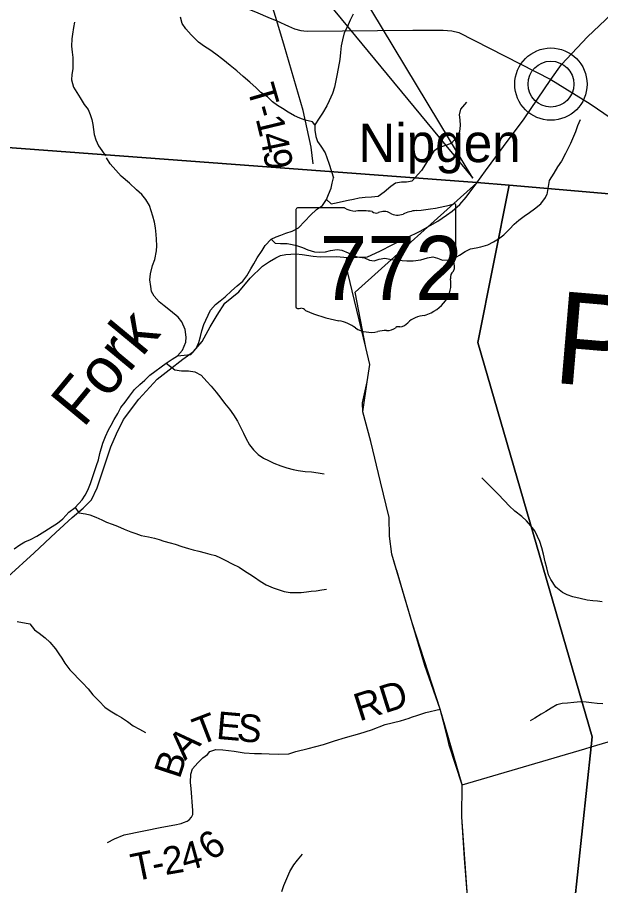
# Model space of a CAD drawing. Extents: x 0 to 34, y 0 to 22.
# Drawn here: x 3.817 to 5.019, y 17.795 to 19.582 of the extents above; entities that cross this region are included whole.
import ezdxf

# ---------------------------------------------------------------- set-up
doc = ezdxf.new("R2010")
doc.units = 0
for name, color, linetype in [('Default', 7, 'Continuous'), ('GM_X_County_Road', 7, 'Continuous'), ('GM_X_County_Text', 7, 'Continuous'), ('GM_X_Minor_River', 7, 'Continuous'), ('GM_X_Minor_River_Text', 7, 'Continuous'), ('GM_X_State_Location', 7, 'Continuous'), ('GM_X_State_Route', 7, 'Continuous'), ('GM_X_State_Shield', 7, 'Continuous'), ('GM_X_Township_Road', 7, 'Continuous'), ('GM_X_Township_Road_Text', 7, 'Continuous'), ('GM_X_Unincorporated', 7, 'Continuous'), ('GM_X_Unincorporated_Location', 7, 'Continuous'), ('GM_X_Unincorporated_Text', 7, 'Continuous'), ('SH_Cut_Line', 7, 'Continuous'), ('SH_Text', 7, 'Continuous')]:
    doc.layers.add(name, color=color, linetype=linetype)

msp = doc.modelspace()

# ---------------------------------------------------------------- linework, layer by layer
at = {"layer": 'Default'}
for p, q in [((4.5136, 19.0159), (4.7643, 19.2414)), ((4.5356, 18.9025), (4.5136, 19.0159)), ((4.5438, 18.8675), (4.5356, 18.9025)), ((4.5384, 18.8319), (4.5438, 18.8675)), ((4.5295, 18.7697), (4.5384, 18.8319)), ((4.5454, 18.7087), (4.5295, 18.7697)), ((4.5658, 18.6257), (4.5454, 18.7087)), ((4.5837, 18.5521), (4.5658, 18.6257)), ((4.5843, 18.5138), (4.5837, 18.5521)), ((4.5891, 18.4769), (4.5843, 18.5138)), ((4.6306, 18.3358), (4.5891, 18.4769)), ((4.6885, 18.1581), (4.6306, 18.3358)), ((4.7336, 18.0018), (4.6885, 18.1581)), ((4.7334, 17.9364), (4.7336, 18.0018)), ((4.7457, 17.7634), (4.7334, 17.9364))]:
    msp.add_line(p, q, dxfattribs=at)
msp.add_lwpolyline([(5.8621, 20.8), (2.8183, 20.8), (3.0244, 19.9995), (3.1893, 19.3592), (4.7641, 19.2419), (4.831, 19.2363), (5.1554, 19.2083), (5.1782, 19.2598), (5.5496, 20.1004), (5.5679, 20.1313), (5.5783, 20.1528), (5.5834, 20.1771), (5.5869, 20.1933), (5.5951, 20.2127), (5.6047, 20.2229), (5.6166, 20.2359)], close=True, dxfattribs=at)
for points in [[(4.7194, 16.7424), (4.6758, 16.8903), (4.9207, 17.3435), (4.9239, 17.3511), (4.937, 17.4953), (4.9996, 18.0806), (5.0018, 18.1008), (4.7661, 18.9124), (4.831, 19.2363), (4.7641, 19.2419), (3.1893, 19.3592), (2.7961, 19.3885), (2.2, 19.4329), (2.2, 14)], [(9, 14), (9, 18.8941), (8.8762, 18.9027), (8.0305, 18.9725), (6.8442, 19.0679), (6.226, 19.1161), (5.8337, 19.1499), (5.3224, 19.1939), (5.1554, 19.2083), (4.831, 19.2363), (4.7661, 18.9124), (5.0018, 18.1008), (4.9996, 18.0806), (4.937, 17.4953), (4.9239, 17.3511), (4.9207, 17.3435), (4.6758, 16.8903), (4.7194, 16.7424)]]:
    msp.add_lwpolyline(points, dxfattribs=at)
at = {"layer": 'GM_X_County_Road'}
for points in [[(4.3522, 19.5749), (4.1318, 20.2937), (4.0556, 20.5466), (3.9987, 20.7384), (3.9908, 20.7664), (3.9869, 20.7867), (3.9826, 20.8)], [(3.8106, 19.8567), (3.8307, 19.8474), (3.8722, 19.8295), (3.898, 19.8193), (3.9145, 19.8144), (3.9359, 19.8139), (3.9841, 19.8144), (4.0229, 19.8108), (4.0448, 19.8072), (4.067, 19.7996), (4.0907, 19.784), (4.1222, 19.7574), (4.1679, 19.715), (4.1864, 19.6956), (4.2033, 19.6726), (4.2288, 19.6388), (4.2486, 19.6219), (4.2614, 19.6133), (4.2873, 19.6013), (4.3128, 19.5911), (4.3334, 19.5824), (4.3522, 19.5749)], [(4.3522, 19.5749), (4.376, 19.5637), (4.3884, 19.5583), (4.4018, 19.5551), (4.408, 19.5543), (4.4144, 19.5531), (4.6324, 19.5555), (4.6948, 19.5557), (4.7129, 19.5541), (4.7273, 19.5504), (4.9164, 19.4541)], [(4.9164, 19.4541), (4.9979, 19.4035), (5.041, 19.3741), (5.05, 19.3665), (5.0594, 19.3519), (5.067, 19.3348), (5.076, 19.3196), (5.0812, 19.3138), (5.0898, 19.3083), (5.1026, 19.3049), (5.1266, 19.2989), (5.1414, 19.2924), (5.1511, 19.2846), (5.1627, 19.2744), (5.1784, 19.2593), (5.1867, 19.2531), (5.1893, 19.2513)], [(3.7978, 18.43), (3.8524, 18.4795), (3.8967, 18.5215), (3.9307, 18.5526), (3.9532, 18.5713), (3.97, 18.589), (3.982, 18.6135), (4.0098, 18.6978), (4.0218, 18.7247), (4.0365, 18.7541), (4.068, 18.7962), (4.1058, 18.8372), (4.1299, 18.8563), (4.1585, 18.878), (4.1806, 18.894), (4.1982, 18.9147), (4.2148, 18.9445), (4.2294, 18.969), (4.2452, 18.9935), (4.2738, 19.0171), (4.2972, 19.0449), (4.3224, 19.0697), (4.3368, 19.0796), (4.3498, 19.0866), (4.3594, 19.0914), (4.3704, 19.0934), (4.3913, 19.0951), (4.4043, 19.0937), (4.4271, 19.0903), (4.4416, 19.0886), (4.476, 19.0897), (4.497, 19.0874)]]:
    msp.add_lwpolyline(points, dxfattribs=at)
at = {"layer": 'GM_X_Minor_River'}
for points in [[(3.935, 19.5717), (3.9333, 19.5611), (3.9309, 19.5474), (3.93, 19.5376), (3.9291, 19.5224), (3.9305, 19.5103), (3.9315, 19.4993), (3.9321, 19.4883), (3.9316, 19.4761), (3.9295, 19.464), (3.9287, 19.453), (3.933, 19.4382), (3.9401, 19.4271), (3.9468, 19.416), (3.9549, 19.4023), (3.9631, 19.3919), (3.9675, 19.382), (3.9712, 19.3713), (3.9733, 19.3611), (3.9747, 19.3512), (3.9758, 19.3409), (3.979, 19.3295), (3.9846, 19.3173), (3.9912, 19.3078), (3.9994, 19.2967)], [(4.4305, 19.3606), (4.4256, 19.3667), (4.4102, 19.3703), (4.3993, 19.3743), (4.3887, 19.3793), (4.3756, 19.3867), (4.3636, 19.3944), (4.3534, 19.4006), (4.3433, 19.4083), (4.3325, 19.4183), (4.3193, 19.4275), (4.3092, 19.4368), (4.2965, 19.4483), (4.2827, 19.4602), (4.2699, 19.4717), (4.2561, 19.4829), (4.2411, 19.4952), (4.2265, 19.506), (4.2141, 19.5149), (4.2029, 19.5222), (4.1905, 19.5311), (4.1759, 19.5457), (4.1647, 19.558), (4.1573, 19.5691), (4.1533, 19.5824)], [(4.5095, 19.5884), (4.503, 19.576), (4.4967, 19.5616), (4.4909, 19.5503), (4.4874, 19.5356), (4.4846, 19.5231), (4.4829, 19.5094), (4.4816, 19.4954), (4.4787, 19.4769), (4.4755, 19.4625), (4.4707, 19.4383), (4.4668, 19.425), (4.4602, 19.4103), (4.4551, 19.3998), (4.4459, 19.3843), (4.4393, 19.3745), (4.4305, 19.3606), (4.43, 19.3496), (4.4321, 19.3363), (4.4361, 19.326), (4.4428, 19.3165), (4.4514, 19.3027), (4.455, 19.2932), (4.4602, 19.2795), (4.4687, 19.2512)], [(4.7426, 19.407), (4.7307, 19.3927), (4.7279, 19.3814), (4.7289, 19.3707), (4.7296, 19.3593), (4.7283, 19.3468), (4.724, 19.3367), (4.711, 19.3224), (4.6977, 19.3176), (4.6852, 19.3132), (4.6756, 19.3061), (4.666, 19.2922), (4.6583, 19.2798), (4.6498, 19.2666), (4.6311, 19.245)], [(4.977, 19.3708), (4.9712, 19.3584), (4.9673, 19.3463), (4.9568, 19.3225), (4.9521, 19.3127), (4.9467, 19.3018), (4.9382, 19.2859), (4.9301, 19.2743), (4.9228, 19.2611), (4.9128, 19.246), (4.9081, 19.2173)], [(3.811, 18.488), (3.8228, 18.4959), (3.833, 18.5019), (3.8444, 18.5068), (3.8577, 18.5139), (3.874, 18.524), (3.8892, 18.5338), (3.9002, 18.5409), (3.9112, 18.5496), (3.9238, 18.5632), (3.9363, 18.5726), (3.9511, 18.5888), (3.9572, 18.5986), (3.9626, 18.6085), (3.9683, 18.6221), (3.976, 18.6448), (3.9803, 18.6596), (3.9845, 18.6709), (3.9872, 18.6842), (3.9938, 18.7054), (3.9988, 18.7194), (4.0053, 18.7326), (4.0107, 18.7424), (4.0172, 18.7542), (4.0248, 18.7666), (4.0309, 18.7791), (4.0393, 18.7897), (4.0488, 18.8021), (4.0591, 18.8157), (4.0698, 18.8259), (4.08, 18.8349), (4.0903, 18.8455), (4.1009, 18.8526), (4.1135, 18.8624), (4.1241, 18.8699), (4.1366, 18.8782), (4.1476, 18.885), (4.1575, 18.8967), (4.1644, 18.9133), (4.1653, 18.9236), (4.1635, 18.9391), (4.1564, 18.9551), (4.1489, 18.9646), (4.1331, 18.9776), (4.1199, 18.9883), (4.1097, 18.996), (4.0992, 19.0078), (4.094, 19.0173), (4.0922, 19.028), (4.0907, 19.0416), (4.0916, 19.0541), (4.0962, 19.0712), (4.1008, 19.0837), (4.1043, 19.1011), (4.1048, 19.1113), (4.1041, 19.125), (4.1034, 19.1352), (4.1023, 19.1485), (4.1001, 19.1603), (4.0964, 19.1728), (4.0931, 19.1839), (4.0894, 19.1949), (4.0823, 19.2071), (4.0736, 19.217), (4.0627, 19.2265), (4.0488, 19.2403), (4.0315, 19.2552), (4.0206, 19.267), (4.009, 19.28), (4.0011, 19.2929)], [(4.1476, 18.885), (4.1751, 18.8881), (4.1857, 18.8999), (4.1914, 18.9128), (4.1948, 18.9246), (4.1978, 18.9368), (4.2016, 18.9493), (4.2058, 18.9588), (4.2104, 18.9691), (4.2157, 18.979), (4.2259, 18.9907), (4.2354, 18.998), (4.2453, 19.0067), (4.2589, 19.0189), (4.2703, 19.0291), (4.2821, 19.039), (4.2904, 19.05), (4.2988, 19.0645), (4.3049, 19.0747), (4.3117, 19.0869), (4.3219, 19.1017), (4.328, 19.112), (4.3402, 19.1253), (4.3508, 19.1302), (4.3603, 19.1336), (4.3705, 19.1374), (4.3838, 19.1416), (4.3967, 19.1488), (4.41, 19.1621), (4.4213, 19.1747), (4.4339, 19.1861), (4.4464, 19.1948), (4.4544, 19.207), (4.4585, 19.2172), (4.4639, 19.2305), (4.4661, 19.2404), (4.4687, 19.2512)], [(4.4544, 19.207), (4.4642, 19.1982), (4.4745, 19.1998), (4.4892, 19.2032), (4.4987, 19.2055), (4.5097, 19.2077), (4.5219, 19.2104), (4.534, 19.2115), (4.5473, 19.2123), (4.5606, 19.2138), (4.5735, 19.2229), (4.5871, 19.2347), (4.5966, 19.2412), (4.6091, 19.2431), (4.6194, 19.2434), (4.6311, 19.245)], [(4.3402, 19.1253), (4.3489, 19.1173), (4.3599, 19.1165), (4.3732, 19.1162), (4.3834, 19.1146), (4.3929, 19.112), (4.4046, 19.1078), (4.4156, 19.1032), (4.4297, 19.0994), (4.4395, 19.0987), (4.452, 19.0994), (4.4623, 19.1021), (4.4763, 19.104), (4.4858, 19.1025), (4.4987, 19.0971), (4.5082, 19.0926), (4.5176, 19.0891), (4.5328, 19.0869), (4.5431, 19.0823), (4.5525, 19.0804), (4.5628, 19.0842), (4.5745, 19.0861), (4.5886, 19.0834), (4.6003, 19.0819), (4.62, 19.0804), (4.6329, 19.0804), (4.6489, 19.0827), (4.6625, 19.0865), (4.6731, 19.0887), (4.683, 19.0861), (4.6936, 19.0823), (4.7065, 19.0827), (4.7187, 19.0865), (4.7281, 19.0922), (4.7403, 19.1001), (4.7509, 19.1051), (4.7627, 19.1077), (4.7721, 19.1093), (4.7866, 19.1134), (4.7987, 19.1199), (4.8089, 19.126), (4.8196, 19.134), (4.8313, 19.1457), (4.8408, 19.1564), (4.8503, 19.1644), (4.8617, 19.1723), (4.8723, 19.1803), (4.8829, 19.1875), (4.8958, 19.1982), (4.9053, 19.2111), (4.9081, 19.2173)], [(4.1241, 18.8699), (4.1417, 18.8566), (4.1557, 18.8543), (4.1701, 18.8539), (4.183, 18.852), (4.1963, 18.8456), (4.208, 18.8326), (4.2167, 18.8227), (4.227, 18.8106), (4.2365, 18.7977), (4.2444, 18.7874), (4.2543, 18.7756), (4.263, 18.7634), (4.271, 18.7505), (4.2789, 18.7353), (4.2831, 18.7258), (4.2884, 18.7159), (4.296, 18.7019), (4.3039, 18.6916), (4.3138, 18.6817), (4.3248, 18.6745), (4.3346, 18.6696), (4.346, 18.6642), (4.36, 18.6585), (4.3726, 18.6547), (4.3858, 18.6513), (4.3961, 18.6494), (4.4105, 18.6471), (4.4234, 18.646), (4.4374, 18.6441), (4.4499, 18.6422)], [(5.0225, 18.3787), (5.013, 18.3798), (5.0028, 18.381), (4.9914, 18.3825), (4.977, 18.3855), (4.9618, 18.389), (4.9501, 18.3928), (4.9406, 18.3981), (4.9269, 18.4087), (4.9167, 18.4247), (4.9118, 18.4346), (4.908, 18.4487), (4.905, 18.4608), (4.9012, 18.4768), (4.8982, 18.4897), (4.8936, 18.5026), (4.8891, 18.5133), (4.8834, 18.5247), (4.8754, 18.5349), (4.8667, 18.5452), (4.8565, 18.5543), (4.8421, 18.5657), (4.8307, 18.5764), (4.8212, 18.5863), (4.8072, 18.6011), (4.7969, 18.611), (4.7852, 18.6228), (4.7746, 18.6342)], [(3.9363, 18.5726), (3.9443, 18.5616), (3.9576, 18.5601), (3.9671, 18.5578), (3.9792, 18.5529), (3.9917, 18.5472), (4.0012, 18.543), (4.0129, 18.5384), (4.0239, 18.5346), (4.0372, 18.5282), (4.0516, 18.5225), (4.0615, 18.5191), (4.0725, 18.5153), (4.0876, 18.5122), (4.0998, 18.5099), (4.1093, 18.5069), (4.1195, 18.5038), (4.1324, 18.5), (4.1426, 18.4974), (4.1563, 18.4928), (4.1699, 18.4886), (4.1794, 18.486), (4.1912, 18.4829), (4.2041, 18.4795), (4.2139, 18.4769), (4.2257, 18.4738), (4.2359, 18.4692), (4.2454, 18.4647), (4.2598, 18.4571), (4.2742, 18.4499), (4.2856, 18.4426), (4.2962, 18.4358), (4.3061, 18.4293), (4.3178, 18.4213), (4.33, 18.4137), (4.3444, 18.4077), (4.3569, 18.4031), (4.3675, 18.4001), (4.3793, 18.3982), (4.3914, 18.3978), (4.4024, 18.3978), (4.4134, 18.3993), (4.4229, 18.4004), (4.4331, 18.4016), (4.4449, 18.4035), (4.4547, 18.405)], [(3.8171, 18.3385), (3.8429, 18.3332), (3.8528, 18.321), (3.8623, 18.3142), (3.8751, 18.3047), (3.8846, 18.2959), (3.896, 18.2823), (3.9032, 18.272), (3.9089, 18.2625), (3.9153, 18.2522), (3.9256, 18.2385), (3.9517, 18.2123), (3.9631, 18.1998), (3.9729, 18.1876), (3.9858, 18.1743), (3.998, 18.1617), (4.009, 18.1541), (4.0222, 18.1462), (4.0317, 18.1408), (4.0442, 18.1321), (4.0563, 18.1237), (4.0692, 18.1165), (4.0818, 18.1097)], [(5.0235, 18.1689), (5.0122, 18.1696), (5.0004, 18.1711), (4.9894, 18.1723), (4.9776, 18.1727), (4.964, 18.1715), (4.9507, 18.1704), (4.9401, 18.1693), (4.9291, 18.1666), (4.9173, 18.1601), (4.9059, 18.1533), (4.8965, 18.1472), (4.8836, 18.1392), (4.8741, 18.1339)], [(4.3626, 17.7827), (4.3668, 17.7949), (4.3744, 17.8139), (4.3786, 17.8234), (4.3873, 17.8371), (4.3949, 17.8469), (4.4048, 17.8595)]]:
    msp.add_lwpolyline(points, dxfattribs=at)
at = {"layer": 'GM_X_State_Route'}
for p, q in [((4.7643, 19.2414), (4.7822, 19.2658)), ((4.7049, 18.0936), (4.6986, 18.1184))]:
    msp.add_line(p, q, dxfattribs=at)
for points in [[(4.7822, 19.2658), (4.8193, 19.3162), (4.8615, 19.3727), (4.9164, 19.4541), (4.9387, 19.4846), (4.9923, 19.5416), (5.0416, 19.5883), (5.0927, 19.6394)], [(4.5988, 18.4442), (4.5891, 18.4769), (4.5843, 18.5138), (4.5837, 18.5521), (4.5658, 18.6257), (4.5454, 18.7087), (4.5295, 18.7697), (4.5287, 18.7883), (4.5384, 18.8319), (4.5438, 18.8675), (4.5356, 18.9025), (4.4935, 19.0756), (4.497, 19.0874), (4.539, 19.0892), (4.564, 19.1007), (4.591, 19.1145), (4.6473, 19.1416), (4.6836, 19.1626), (4.7013, 19.1745), (4.7133, 19.1828), (4.7289, 19.1963), (4.742, 19.2115), (4.7643, 19.2414)], [(4.6986, 18.1184), (4.6885, 18.1581), (4.6571, 18.2477), (4.6306, 18.3358), (4.6082, 18.4124), (4.5991, 18.4432), (4.5988, 18.4442)], [(4.676, 16.8898), (4.6315, 17.0374), (4.6235, 17.065), (4.6232, 17.0732), (4.6258, 17.0849), (4.6542, 17.1544), (4.6904, 17.2283), (4.6988, 17.2582), (4.7021, 17.298), (4.7044, 17.3531), (4.7062, 17.4355), (4.7088, 17.5099), (4.7121, 17.5596), (4.7312, 17.6208), (4.7459, 17.673), (4.7476, 17.7095), (4.7457, 17.7634), (4.7386, 17.8513), (4.7334, 17.9364), (4.7336, 18.0018), (4.7074, 18.0837), (4.7049, 18.0936)]]:
    msp.add_lwpolyline(points, dxfattribs=at)
at = {"layer": 'GM_X_State_Shield'}
for p, q in [((4.3915, 19.1862), (4.3915, 18.986)), ((4.4913, 19.1896), (4.3947, 19.1896)), ((4.7211, 19.0899), (4.7211, 19.1946)), ((4.721, 19.0899), (4.7211, 19.0899))]:
    msp.add_line(p, q, dxfattribs=at)
for centre, major_axis, start_param, end_param in [((4.6037, 19.4624), (0.3495, 0), 4.814394, 5.042369), ((4.7174, 19.195), (0.00367, 0), 6.141152, 7.989035), ((4.3953, 19.1866), (0.00382, 0), 1.712693, 3.28349), ((4.5142, 19.2128), (0.037, 0), 4.042523, 4.731795), ((4.5265, 19.0772), (0.133, 0), 1.404758, 1.657858), ((4.5567, 19.1876), (0.0107, 0), 3.836095, 5.185415), ((4.5724, 19.1645), (0.0222, 0), 0.950623, 2.079405), ((4.6011, 19.1962), (0.0267, 0), 4.081561, 5.145723), ((4.6482, 19.1285), (0.0703, 0), 1.699011, 2.107814), ((4.7172, 19.0895), (0.00393, 0), 5.05454, 6.418171), ((4.7202, 19.0822), (0.00568, 0), 1.883978, 3.671073), ((4.6841, 19.069), (0.0341, 0), 5.934695, 6.695948), ((4.7342, 19.0461), (0.0248, 0), 2.387724, 3.262537), ((4.6232, 19.0327), (0.0874, 0), 5.101752, 6.440018), ((4.3953, 18.9856), (0.00385, 0), 3.00124, 4.508301), ((4.3959, 19.0061), (0.0294, 0), 4.665946, 4.897461), ((4.4019, 18.9745), (0.0106, 0), 0.519207, 1.627899), ((4.5357, 19.1543), (0.2524, 0), 4.195997, 4.488961), ((4.6601, 18.9299), (0.0479, 0), 1.647645, 2.488434), ((4.4605, 18.8961), (0.079, 0), 0.823519, 1.323587), ((4.6026, 18.9391), (0.00752, 0), 1.147584, 2.315152), ((4.5994, 18.9666), (0.0282, 0), 4.937069, 5.64225), ((4.5459, 18.9735), (0.0501, 0), 4.026481, 4.996735), ((4.5748, 18.9043), (0.0412, 0), 1.495662, 1.94098), ((4.5785, 18.9585), (0.0267, 0), 4.691044, 5.507374)]:
    msp.add_ellipse(centre, major_axis=major_axis, ratio=0.8, start_param=start_param, end_param=end_param, dxfattribs=at)
at = {"layer": 'GM_X_Township_Road'}
msp.add_line((4.7336, 18.0018), (4.9867, 18.0763), dxfattribs=at)
for points in [[(4.4266, 19.2801), (4.4226, 19.3149), (4.4063, 19.39), (4.3677, 19.5221), (4.3522, 19.5749)], [(4.9867, 18.0763), (4.9999, 18.0801), (5.5456, 18.2407)], [(4.3562, 18.0654), (4.377, 18.0656), (4.391, 18.0707), (4.4164, 18.0765), (4.4479, 18.0853), (4.4711, 18.0926), (4.4938, 18.0996), (4.523, 18.108), (4.5469, 18.1153), (4.575, 18.126), (4.6065, 18.134), (4.6247, 18.1395), (4.6296, 18.1411)], [(4.6296, 18.1411), (4.6422, 18.1453), (4.6593, 18.1509), (4.6885, 18.1581)], [(4.16, 17.9245), (4.1675, 17.9275), (4.1717, 17.9301), (4.1763, 17.9353), (4.179, 17.941), (4.1791, 17.9494), (4.1754, 17.9946), (4.1744, 18.0071), (4.1746, 18.0238), (4.1785, 18.0348), (4.1896, 18.0476), (4.1995, 18.0573), (4.2091, 18.0644), (4.214, 18.0704), (4.2262, 18.0749), (4.2409, 18.0739), (4.264, 18.0714), (4.2847, 18.0681), (4.3059, 18.0664), (4.3206, 18.0662), (4.3365, 18.0657), (4.3562, 18.0654)], [(4.0033, 17.8834), (4.0177, 17.8908), (4.0375, 17.8989), (4.1152, 17.9152), (4.1421, 17.9194), (4.1553, 17.9227), (4.16, 17.9245)]]:
    msp.add_lwpolyline(points, dxfattribs=at)
at = {"layer": 'GM_X_Unincorporated'}
for radius in [0.0744, 0.0472]:
    msp.add_circle((4.9167, 19.4444), radius, dxfattribs=at)
at = {"layer": 'GM_X_Unincorporated_Location'}
msp.add_line((4.9167, 19.4444), (4.9167, 19.4444), dxfattribs=at)
at = {"layer": 'SH_Cut_Line'}
for points in [[(9, 18.8941), (9, 20.8), (2.2, 20.8), (2.2, 19.4329), (2.7961, 19.3885), (3.1893, 19.3592), (4.7641, 19.2419), (4.831, 19.2363), (5.1554, 19.2083), (5.3224, 19.1939), (5.8337, 19.1499), (6.226, 19.1161), (6.8442, 19.0679), (8.0305, 18.9725), (8.8762, 18.9027)], [(2.2, 19.4329), (2.2, 14), (9, 14), (9, 18.8941), (8.8762, 18.9027), (8.0305, 18.9725), (6.8442, 19.0679), (6.226, 19.1161), (5.8337, 19.1499), (5.3224, 19.1939), (5.1554, 19.2083), (4.831, 19.2363), (4.7641, 19.2419), (3.1893, 19.3592), (2.7961, 19.3885)]]:
    msp.add_lwpolyline(points, close=True, dxfattribs=at)
at = {"layer": 'SH_Text'}
msp.add_lwpolyline([(4.7557, 19.2507), (3.9194, 20.6364), (3.9194, 20.2631)], close=True, dxfattribs=at)

# ---------------------------------------------------------------- texts
at = {"layer": 'GM_X_County_Text'}
msp.add_text('PIKE COUNTY', height=0.189394, rotation=355.1489, dxfattribs=at).set_placement((4.9178, 18.83))
at = {"layer": 'GM_X_Minor_River_Text'}
msp.add_text('Fork', height=0.09469, rotation=50.3786, dxfattribs=at).set_placement((3.9532, 18.735))
at = {"layer": 'GM_X_State_Location'}
for s in ['s', 'r']:
    msp.add_text(s, height=0.000189, dxfattribs=at).set_placement((4.5526, 19.0728))
msp.add_text('772', height=0.000189, rotation=0, dxfattribs=at).set_placement((4.4857, 19.059))
at = {"layer": 'GM_X_State_Shield'}
msp.add_text('772', height=0.13184, dxfattribs=at).set_placement((4.4405, 19.0001))
at = {"layer": 'GM_X_Township_Road_Text'}
for s, height, rotation, p in [('T', 0.0568, 286.2003, (4.2902, 19.4362)), ('-', 0.0568, 285.4393, (4.302, 19.3956)), ('1', 0.0568, 283.6109, (4.3081, 19.3736)), ('4', 0.0568, 281.7442, (4.3162, 19.34)), ('9', 0.0568, 279.6048, (4.3233, 19.3063)), ('RD', 0.05682, 17.502, (4.5219, 18.1324)), ('T', 0.0568, 21, (4.1929, 18.0826)), ('E', 0.0568, 354.9623, (4.2259, 18.0969)), ('S', 0.0568, 353.4767, (4.2679, 18.0932)), ('A', 0.0568, 44.7656, (4.1626, 18.0507)), ('B', 0.0568, 71.8378, (4.1518, 18.0124)), ('6', 0.0568, 37.8798, (4.2179, 17.8435)), ('2', 0.0568, 9.8208, (4.1222, 17.8161)), ('4', 0.0568, 15.5058, (4.1627, 17.8234)), ('T', 0.0568, 11.647, (4.0582, 17.803)), ('-', 0.0568, 11.3773, (4.0997, 17.8115))]:
    msp.add_text(s, height=height, rotation=rotation, dxfattribs=at).set_placement(p)
at = {"layer": 'GM_X_Unincorporated_Text'}
msp.add_text('Nipgen', height=0.07898, rotation=0, dxfattribs=at).set_placement((4.5199, 19.2838))

doc.saveas('drawing.dxf')
